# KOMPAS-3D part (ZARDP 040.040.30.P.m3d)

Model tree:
1. Плоскость XY
2. Плоскость ZX
3. Плоскость ZY
4. Ось X
5. Ось Y
6. Ось Z
7. Начало координат
8. Булева операция:1
9. Булева операция:2
10. Булева операция:3
11. Булева операция:4
12. Булева операция:5
13. Булева операция:6
